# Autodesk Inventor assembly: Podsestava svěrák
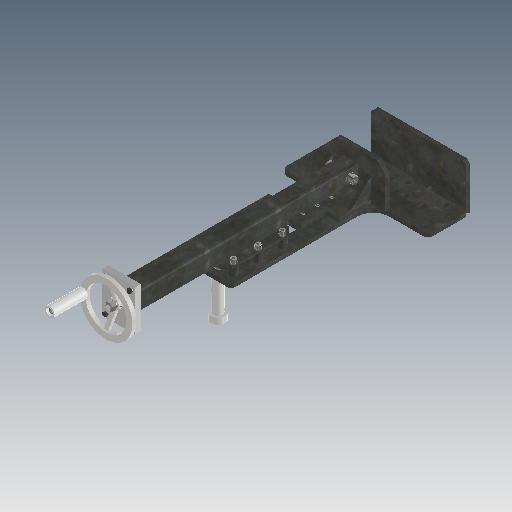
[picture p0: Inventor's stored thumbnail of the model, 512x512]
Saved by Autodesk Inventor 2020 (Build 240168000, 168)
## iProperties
Created: 2025-04
Part Number: Podsestava svěrák
Document SubType Name: Assembly
Designer: doma
Author: doma
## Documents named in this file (30)
- C:\Users\doma\Desktop\Pásovka záloha\Workgroups\NotInProject\Podsestava svěrák.iam
- C:\Users\doma\Desktop\Pásovka záloha\Workgroups\NotInProject\Svařenec svěrák tělo.iam
- C:\Users\doma\Desktop\Pásovka záloha\Workgroups\NotInProject\Svařenec pohyblivé čelisti.iam
- C:\Users\doma\Desktop\Pásovka záloha\Workgroups\NotInProject\Vedení čelisti.ipt
- C:\Users\doma\Desktop\Pásovka záloha\Workgroups\NotInProject\Zajištění pohyblivé čelisti.ipt
- C:\Users\doma\Desktop\Pásovka záloha\Workgroups\NotInProject\Podložka v20.ipt
- C:\Users\doma\Desktop\Pásovka záloha\Workgroups\NotInProject\Svařenec pohyb čelisti.iam
- C:\Users\doma\Desktop\Pásovka záloha\Workgroups\NotInProject\Jekl 5.ipt
- C:\Users\doma\Desktop\Pásovka záloha\Workgroups\NotInProject\Matice svěráku.ipt
- C:\Users\doma\Documents\Inventor\Content Center Files\R2020\cs-CZ\CSN 02 3481  B\CSN 02 3481 - B - 16x22x12.ipt
- C:\Users\doma\Desktop\Pásovka záloha\Workgroups\NotInProject\Domeček ložiska svěráku.ipt
- C:\Users\doma\Desktop\Pásovka záloha\Workgroups\NotInProject\Šroub svěráku.ipt
- C:\Users\doma\Documents\Inventor\Content Center Files\R2020\cs-CZ\ISO 4032(2)\ISO 4032 - M12 - ISO.ipt
- C:\Users\doma\Desktop\Pásovka záloha\Workgroups\NotInProject\Klika.ipt
- C:\Users\doma\Documents\Inventor\Content Center Files\R2020\cs-CZ\CSN 02 1187\CSN 02 1187 - M4 x 0,7 x 10.ipt
- C:\Users\doma\Documents\Inventor\Content Center Files\R2020\cs-CZ\CSN 02 1740\CSN 02 1740 - 12.ipt
- C:\Users\doma\Desktop\Pásovka záloha\Workgroups\NotInProject\Rukojeť.ipt
- C:\Users\doma\Desktop\Pásovka záloha\Workgroups\NotInProject\Podpěra svěráku.ipt
- C:\Users\doma\Documents\Inventor\Content Center Files\R2020\cs-CZ\ISO 2338(2)\ISO 2338 - 3 h8 x 40.ipt
- C:\Users\doma\Documents\Inventor\Content Center Files\R2020\cs-CZ\CSN 02 1741\CSN 02 1741 - 8.ipt
- C:\Users\doma\Documents\Inventor\Content Center Files\R2020\cs-CZ\ISO 4762(2)\ISO 4762 - M8 x 40ISO.ipt
- C:\Users\doma\Documents\Inventor\Content Center Files\R2020\cs-CZ\CSN 02 1741\CSN 02 1741 - 6.ipt
- C:\Users\doma\Documents\Inventor\Content Center Files\R2020\cs-CZ\ISO 4018\ISO 4018 - M6 x 16.ipt
- C:\Users\doma\Documents\Inventor\Content Center Files\R2020\cs-CZ\ISO 4762(2)\ISO 4762 - M5 x 25ISO.ipt
- C:\Users\doma\Documents\Inventor\Content Center Files\R2020\cs-CZ\CSN 02 1703\CSN 02 1703 - 13.ipt
- C:\Users\doma\Documents\Inventor\Content Center Files\R2020\cs-CZ\CSN 02 1741\CSN 02 1741 - 12.ipt
- C:\Users\doma\Documents\Inventor\Content Center Files\R2020\cs-CZ\ISO 4762(2)\ISO 4762 - M12 x 60ISO.ipt
- C:\Users\doma\Documents\Inventor\Content Center Files\R2020\cs-CZ\ISO 4762(2)\ISO 4762 - M10 x 80ISO.ipt
- C:\Users\doma\Desktop\Pásovka záloha\Libraries\Content Center Files\cs-CZ\CSN 02 4730\CSN 02 4730 - 511 03 - 17 x 30 x 9.ipt
- C:\Users\doma\Documents\Inventor\Content Center Files\R2020\cs-CZ\ISO 4762(2)\ISO 4762 - M8 x 25ISO.ipt
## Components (55 placed, 29 different names)
1. Svařenec svěrák tělo:1 [sub-assembly] — Úhel:1
2. Svařenec pohyblivé čelisti:1 [sub-assembly]
3. Vedení čelisti:1
4. Zajištění pohyblivé čelisti:1
5. Podložka v20:1
6. Podložka v20:2
7. Podložka v20:3
8. Podložka v20:4
9. Podložka v20:5
10. Podložka v20:6
11. Svařenec pohyb čelisti:1 [sub-assembly]
12. Jekl 5:1
13. Matice svěráku:1
14. CSN 02 3481 B B - 16x22x12:1
15. Domeček ložiska svěráku:1
16. Šroub svěráku:1 — Proti sobě:46
17. CSN 02 4730 511 03 - 17 x 30 x 9:1 — Proti sobě:46
18. ISO 4032 M12:1
19. Klika:1
20. CSN 02 1187 M4 x 10:1
21. CSN 02 1740 12:1
22. Rukojeť:1
23. Podpěra svěráku:1 — Úhel:1
24. ISO 2338 3 h8 x 40:1
25. ISO 2338 3 h8 x 40:2
26. CSN 02 1741 8:1
27. CSN 02 1741 8:2
28. CSN 02 1741 8:3
29. CSN 02 1741 8:4
30. CSN 02 1741 8:5
31. CSN 02 1741 8:6
32. ISO 4762 M8 x 40:1
33. ISO 4762 M8 x 40:2
34. ISO 4762 M8 x 40:3
35. ISO 4762 M8 x 40:4
36. ISO 4762 M8 x 40:5
37. ISO 4762 M8 x 40:6
38. CSN 02 1741 6:1
39. CSN 02 1741 6:2
40. CSN 02 1741 6:3
41. CSN 02 1741 6:4
42. ISO 4018 M6 x 16:1
43. ISO 4018 M6 x 16:2
44. ISO 4018 M6 x 16:3
45. ISO 4018 M6 x 16:4
46. ISO 4762 M5 x 25:1
47. ISO 4762 M5 x 25:2
48. ISO 4762 M5 x 25:3
49. CSN 02 1703 13:1
50. CSN 02 1741 12:1
51. ISO 4032 M12:2
52. ISO 4762 M12 x 60:1
53. ISO 4762 M10 x 80:1
54. CSN 02 1741 8:7
55. ISO 4762 M8 x 25:1
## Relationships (2: Angle 1, Mate 1)
- Úhel:1 [Angle]: Svařenec svěrák tělo:1 ↔ Podpěra svěráku:1
- Proti sobě:46 [Mate]: Šroub svěráku:1 ↔ CSN 02 4730 511 03 - 17 x 30 x 9:1
## Named parameters: d31_d61 = 0, d32_d62 = 0, d33_d63 = 0, d34_d64 = 0, d35_d65 = 0, d36_d66 = 0, d37_d67 = 0, d38_d68 = 0, d39_d69 = 0, d40_d70 = 0, d41_d71 = 0, d42_d72 = 0, d43_d73 = 0, d44_d74 = 0, d45_d75 = 0, d46_d50 = 0, d47_d51 = 0, d48_d52 = 0, d49_d53 = 0, d50_d54 = 0, d51_d55 = 0, d52_d56 = 0, d53_d57 = 0
